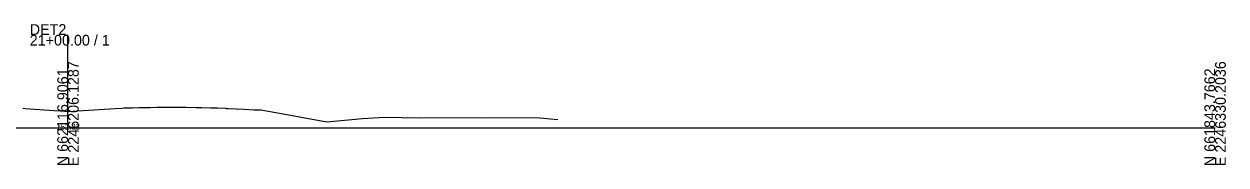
# Model space of a CAD drawing. Extents: x -26 to 603, y -10 to 9526.
# Drawn here: x 288.5 to 602.8, y 3990.3 to 4027.2 of the extents above; entities that cross this region are included whole.
import ezdxf

# ---------------------------------------------------------------- set-up
doc = ezdxf.new("R2010")
doc.units = 0
for name, color, linetype in [('Exist Cross Section Cell', 7, 'Continuous'), ('Exist XS Center Line Elevation Label', 7, 'Continuous'), ('Exist XS Ground Line', 7, 'Continuous')]:
    doc.layers.add(name, color=color, linetype=linetype)

msp = doc.modelspace()

# ---------------------------------------------------------------- linework, layer by layer
at = {"layer": 'Exist Cross Section Cell'}
for p, q in [((300, 4000), (300, 4024.38)), ((0, 4000), (300, 4000)), ((300, 4000), (600, 4000))]:
    msp.add_line(p, q, dxfattribs=at)
at = {"layer": 'Exist XS Ground Line'}
for p, q in [((288.15, 4005.15), (288.86, 4005.06)), ((288.86, 4005.06), (296.28, 4004.58)), ((302.57, 4004.46), (312.33, 4005.11)), ((312.33, 4005.11), (314.07, 4005.21)), ((314.07, 4005.21), (314.63, 4005.24)), ((314.63, 4005.24), (315.15, 4005.26)), ((315.15, 4005.26), (315.61, 4005.28)), ((315.61, 4005.28), (316.86, 4005.31)), ((316.86, 4005.31), (318.57, 4005.34)), ((318.57, 4005.34), (319.47, 4005.35)), ((319.47, 4005.35), (321.45, 4005.38)), ((321.45, 4005.38), (323.24, 4005.41)), ((323.24, 4005.41), (324.06, 4005.42)), ((324.06, 4005.42), (326.04, 4005.45)), ((326.04, 4005.45), (327.08, 4005.47)), ((327.08, 4005.47), (327.46, 4005.46)), ((327.46, 4005.46), (328.05, 4005.46)), ((328.05, 4005.46), (329.55, 4005.44)), ((329.55, 4005.44), (330.8, 4005.41)), ((330.8, 4005.41), (333.54, 4005.37)), ((333.54, 4005.37), (335.04, 4005.34)), ((335.04, 4005.34), (337.39, 4005.3)), ((337.39, 4005.3), (339.08, 4005.27)), ((339.08, 4005.27), (341.2, 4005.19)), ((341.2, 4005.19), (341.47, 4005.14)), ((341.47, 4005.14), (341.85, 4005.12)), ((341.85, 4005.12), (346.03, 4004.91)), ((346.03, 4004.91), (348.6, 4004.78)), ((348.6, 4004.78), (349.05, 4004.76)), ((349.05, 4004.76), (350.43, 4004.75)), ((350.43, 4004.75), (353.4, 4004.22)), ((296.28, 4004.58), (298.04, 4004.46)), ((298.04, 4004.46), (300.26, 4004.31)), ((300.26, 4004.31), (301.39, 4004.39)), ((301.39, 4004.39), (302.57, 4004.46)), ((353.4, 4004.22), (367.71, 4001.61)), ((367.71, 4001.61), (377.03, 4002.5)), ((377.03, 4002.5), (382.62, 4002.84)), ((382.62, 4002.84), (392.18, 4002.66)), ((392.18, 4002.66), (409.19, 4002.75)), ((409.19, 4002.75), (423.38, 4002.66)), ((423.38, 4002.66), (428.08, 4002.25))]:
    msp.add_line(p, q, dxfattribs=at)

# ---------------------------------------------------------------- texts
at = {"layer": 'Exist Cross Section Cell'}
for s, p in [('DET2', (290, 4024.38)), ('21+00.00 / 1', (290, 4021.58))]:
    msp.add_text(s, height=2.8, dxfattribs=at).set_placement(p)
for s, p in [('E 2246206.1287', (302.8, 3990)), ('E 2246330.2036', (602.8, 3990)), ('N 662116.9061', (300, 3990)), ('N 661843.7662', (600, 3990))]:
    msp.add_text(s, height=2.8, rotation=90, dxfattribs=at).set_placement(p)
at = {"layer": 'Exist XS Center Line Elevation Label'}
msp.add_text('152.33', height=1.5, dxfattribs=at).set_placement((296.99, 3999.58))

doc.saveas('drawing.dxf')
